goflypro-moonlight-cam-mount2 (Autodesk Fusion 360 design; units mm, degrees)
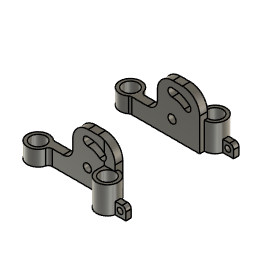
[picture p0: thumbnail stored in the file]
sketch "Skizze1" plane through (0, 0, 0) normal (0, 0, 1) x axis (1, 0, 0)
  line L1 (-8.0404, 2) -> (10, 2)
  line L2 (7.2, 0) -> (-7.2, 0)
  line L3 (7.2, 0) -> (7.2, -2)
  line L4 (10, 0.8) -> (10, 2)
  line L5 (-1, 0) -> (-1, 2)
  line L6 (10, 0) -> (7.2, 0)
  line L7 (10, 0) -> (10, 0.8)
  circle C1 centre (-10, 0) radius 2
  circle C2 centre (10, -2) radius 2
  circle C3 centre (-10, 0) radius 2.8
  circle C4 centre (10, -2) radius 2.8
  point P8 (-7.2, 0)
  point P9 (7.2, -2)
  point P11 (10, 0.8)
  point P7 (-8.0404, 2)
  point P12 (-1, 2)
  point P13 (-1, 0)
  point P14 (10, 0)
  concentric C1 C3
  concentric C2 C4
  horizontal L1
  coincident C3 P8
  horizontal L2
  coincident C4 P9
  tangent C4 L3
  perpendicular L2 L3
  coincident C4 P11
  perpendicular L1 L4
  coincident C3 P7
  perpendicular L2 L5
  coincident L1 P12
  coincident L2 P13
  coincident C2 P14
  tangent C2 L6
  perpendicular L6 L7
  dimension "d1" diameter C1 = 4
  dimension "d2" diameter C2 = 4
  dimension "d3" diameter C3 = 5.6
  dimension "d4" diameter C4 = 5.6
extrude "Extrusion1" new body sketch "Skizze1" profile of C1 C3 L1 L2 L5 along normal blind 4 bodies "GoFlyPro - Moonlight-cam mount2 - left"
extrude "Extrusion5" new body sketch "Skizze1" profile of C2 C4 L3 L6 L7 along normal blind 7
extrude "Extrusion8" add sketch "Skizze1" profile of C4 L1 L2 L4 L5 L6 L7 along normal blind 13
sketch "Skizze2" plane through (0, 2, 0) normal (0, 1, 0) x axis (1, 0, 0)
  circle C1 centre (2.8, -4.25) radius 1.05
  circle C2 centre (2.8, -4.25) radius 4.95
  circle C3 centre (2.8, -4.25) radius 7.05
  circle C4 centre (2.8, -10.25) radius 1.05
  circle C5 centre (6.6567, -8.8463) radius 1.05
  concentric C1 C2
  concentric C2 C3
  dimension "d8" diameter C1 = 2.1
  dimension "d32" diameter C4 = 2.1
  dimension "d64" diameter C5 = 2.1
extrude "Extrusion2" cut sketch "Skizze2" against normal blind 2
fillet "Abrundung12" radius 1
fillet "Abrundung13" radius 1
fillet "Abrundung14" radius 2.5
fillet "Abrundung15" radius 4
fillet "Abrundung16" radius 4.5
work_plane "Arbeitsebene" AlongDistance 12
sketch "Skizze3" plane through (0, 0, 0) normal (0, 0, 1) x axis (1, 0, 0)
  line L1 (12.5, -2.7) -> (15.5, -2.7)
  line L2 (12.5, -1.3) -> (12.5, -2.7)
  line L3 (15.5, -1.3) -> (12.5, -1.3)
  line L4 (15.5, -2.7) -> (15.5, -1.3)
  horizontal L1
  vertical L2
  horizontal L3
  vertical L4
extrude "Extrusion9" add sketch "Skizze3" along normal blind 3
sketch "Skizze4" plane through (0, -2.7, 0) normal (0, -1, 0) x axis (1, 0, 0)
  line L1 (12.7111, 0) -> (12.7111, 3)
  line L2 (15.5, 0) -> (12.7111, 0)
  line L3 (15.5, 3) -> (15.5, 0)
  line L4 (12.7111, 3) -> (15.5, 3)
  circle C1 centre (14, 1.5) radius 0.75
  dimension "d77" diameter C1 = 1.5
extrude "Extrusion10" cut sketch "Skizze4" profile of C1 against normal blind 1.4
fillet "Abrundung19" radius 1
mirror "Spiegeln" mirrorStitchTolerance 0.1 bodies "GoFlyPro - Moonlight-cam mount2 - right"
named bodies: "GoFlyPro - Moonlight-cam mount2 - left", "GoFlyPro - Moonlight-cam mount2 - right"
